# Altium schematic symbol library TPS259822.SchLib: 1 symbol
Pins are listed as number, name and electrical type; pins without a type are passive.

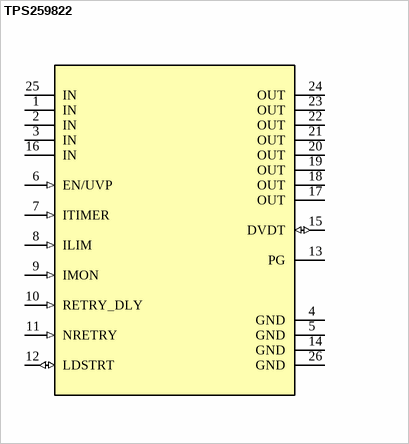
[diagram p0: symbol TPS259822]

## TPS259822
designator U?
pins: 1 IN (power), 2 IN (power), 3 IN (power), 4 GND (power), 5 GND (power), 6 EN/UVP (in), 7 ITIMER (in), 8 ILIM (in), 9 IMON (in), 10 RETRY_DLY (in), 11 NRETRY (in), 12 LDSTRT (io), 13 PG (oc), 14 GND (power), 15 DVDT (io), 16 IN (power), 17 OUT (power), 18 OUT (power), 19 OUT (power), 20 OUT (power), 21 OUT (power), 22 OUT (power), 23 OUT (power), 24 OUT (power), 25 IN (power), 26 GND (power)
